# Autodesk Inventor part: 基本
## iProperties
Created: 2001-06
Part Number: 基本
Document SubType Name: ﾓﾃﾞﾘﾝｸﾞ
Designer: Administrator
Control State: 0
Master: False
Checked Out: False
Shininess: 20.0
Length Units: 11269
Angle Units: 11279
Time Units: 11290
Mass Units: 11283
Length Display Precision: 3
Angle Display Precision: 2
Density: 0.0
Volumn: 0.0
Area: 0.0
PropertySet Name: Model Information
Author: Administrator
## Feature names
1. 押し出し1 [Extrusion]
